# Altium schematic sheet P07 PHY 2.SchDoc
size 420 x 297 mm
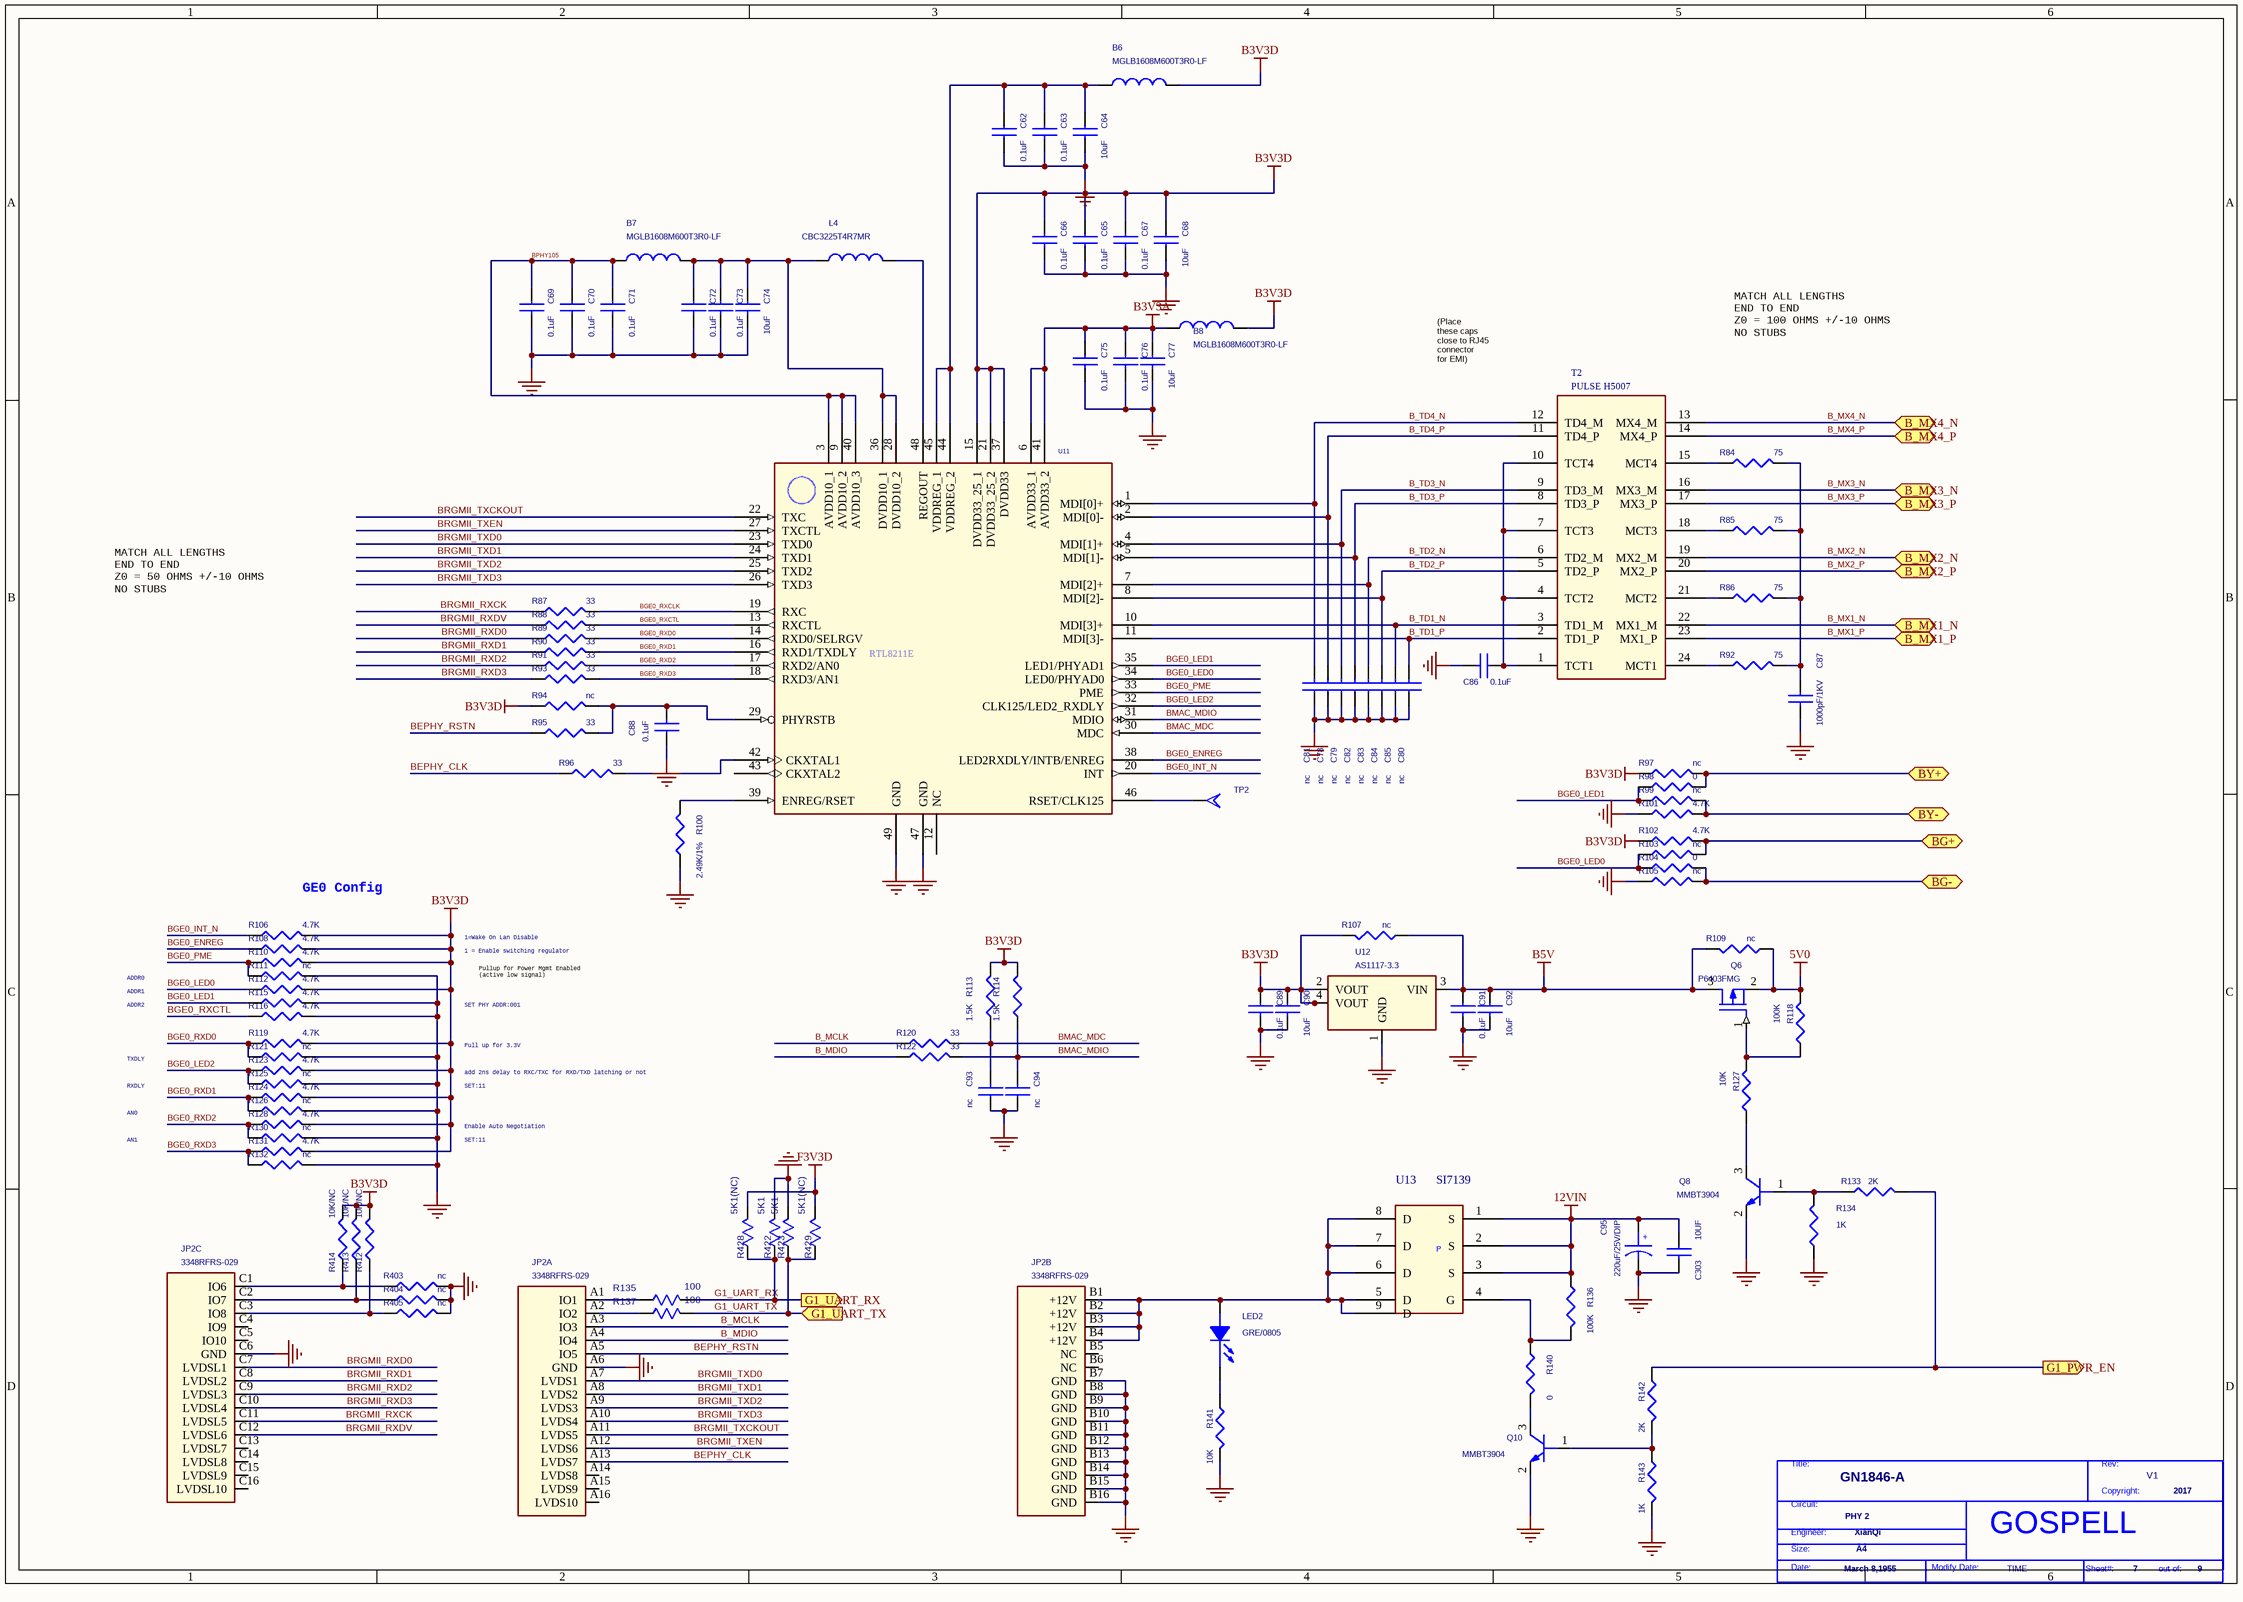
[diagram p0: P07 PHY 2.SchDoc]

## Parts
*  Doc: PHY 2  Page Count: 9  Page Number: 7  Page Create Date: March 8,1955  Page Size: A4  RevCode: V1  Title: GN1846-A  Copyright: 2017  Engineer: XianQi  Page Modify Date: TIME  (hidden comment: GOSPELL)  (graphical)
B6  MGLB1608M600T3R0-LF  [L0603]
B7  MGLB1608M600T3R0-LF  [L0603]
B8  MGLB1608M600T3R0-LF  [L0603]
C62  0.1uF  [0402C]
C63  0.1uF  [0402C]
C64  10uF  [C0603]
C65  0.1uF  [0402C]
C66  0.1uF  [0402C]
C67  0.1uF  [0402C]
C68  10uF  [C0603]
C69  0.1uF  [0402C]
C70  0.1uF  [0402C]
C71  0.1uF  [0402C]
C72  0.1uF  [0402C]
C73  0.1uF  [0402C]
C74  10uF  [C0603]
C75  0.1uF  [0402C]
C76  0.1uF  [0402C]
C77  10uF  [C0603]
C78  nc  [0402C]
C79  nc  [0402C]
C80  nc  [0402C]
C81  nc  [0402C]
C82  nc  [0402C]
C83  nc  [0402C]
C84  nc  [0402C]
C85  nc  [0402C]
C86  0.1uF  [0402C]
C87  1000pF/1KV  [C1206]
C88  0.1uF  [0402C]
C89  0.1uF  [0402C]
C90  10uF  [C0603]
C91  0.1uF  [0402C]
C92  10uF  [C0603]
C93  nc  [0402C]
C94  nc  [0402C]
C95  220uF/25V/DIP  [CE8X3.5]
C303  10UF  [C1206]
JP2  3348RFRS-029  [3348RFRS-029]  (parts A,B,C of 3)
L4  CBC3225T4R7MR  [FB0805]
LED2  GRE/0805  [LED0805]
Q6  P6403FMG  [SOT23]
Q8  MMBT3904  [SOT23]
Q10  MMBT3904  [SOT23]
R84  75  [0402R]
R85  75  [0402R]
R86  75  [0402R]
R87  33  [0402R]
R88  33  [0402R]
R89  33  [0402R]
R90  33  [0402R]
R91  33  [0402R]
R92  75  [0402R]
R93  33  [0402R]
R94  nc  [0402R]
R95  33  [0402R]
R96  33  [0402R]
R97  nc  [0402R]
R98  0  [0402R]
R99  nc  [0402R]
R100  2.49K/1%  [0402R]
R101  4.7K  [0402R]
R102  4.7K  [0402R]
R103  nc  [0402R]
R104  0  [0402R]
R105  nc  [0402R]
R106  4.7K  [0402R]
R107  nc  [R0603]
R108  4.7K  [0402R]
R109  nc  [R0603]
R110  4.7K  [0402R]
R111  nc  [0402R]
R112  4.7K  [0402R]
R113  1.5K  [0402R]
R114  1.5K  [0402R]
R115  4.7K  [0402R]
R116  4.7K  [0402R]
R118  100K  [0402R]
R119  4.7K  [0402R]
R120  33  [0402R]
R121  nc  [0402R]
R122  33  [0402R]
R123  4.7K  [0402R]
R124  4.7K  [0402R]
R125  nc  [0402R]
R126  nc  [0402R]
R127  10K  [0402R]
R128  4.7K  [0402R]
R130  nc  [0402R]
R131  4.7K  [0402R]
R132  nc  [0402R]
R133  2K  [0402R]
R134  1K  [0402R]
R135  100  [0402R]
R136  100K  [R0603]
R137  100  [0402R]
R140  0  [0402R]
R141  10K  [0402R]
R142  2K  [0402R]
R143  1K  [0402R]
R403  nc  [0402R]
R404  nc  [0402R]
R405  nc  [0402R]
R412  10K/NC  [0402R]
R413  10K/NC  [0402R]
R414  10K/NC  [0402R]
R422  5K1  [0402R]
R423  5K1  [0402R]
R428  5K1(NC)  [0402R]
R429  5K1(NC)  [0402R]
T2  PULSE H5007  [H5007-H]
TP2  T POINT A  [TP_G]  (value not drawn)
U11  RTL8211D  [QFN-48P-RTL8211]  (value not drawn)
U12  AS1117-3.3  [SOT223]
U13  SI7139  [PowerPAKSO8]

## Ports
B_MX1_N (bidir), B_MX1_P (bidir), B_MX2_N (bidir), B_MX2_P (bidir), B_MX3_N (bidir), B_MX3_P (bidir), B_MX4_N (bidir), B_MX4_P (bidir), BG+ (bidir), BG- (bidir), BY+ (bidir), BY- (bidir), G1_PWR_EN (out), G1_UART_RX (out), G1_UART_TX (in)

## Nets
5V0: Q6.2(SOURCE) R109.2 R118.1
12VIN: C95.1 C303.1 R136.2 U13.1(S) U13.2(S) U13.3(S)
B3V3A: B8.1 C75.1 C76.1 C77.1 U11.6(AVDD33_1) U11.41(AVDD33_2)
B3V3D: B6.2 B8.2 C65.1 C66.1 C67.1 C68.1 C89.1 C90.1 R94.1 R97.1 R102.1 R106.2 R107.1 R108.2 R110.2 R112.2 R113.2 R114.2 R119.2 R123.2 R124.2 R128.2 R131.2 R412.2 R413.2 R414.2 U11.15(DVDD33_25_1) U11.21(DVDD33_25_2) U11.37(DVDD33) U12.2(VOUT) U12.4(VOUT)
B5V: C91.1 C92.1 Q6.3(DRAIN) R107.2 R109.1 U12.3(VIN)
F3V3D: R428.2(B) R429.2(B)
GND: C62.2 C63.2 C64.2 C65.2 C66.2 C67.2 C68.2 C69.2 C70.2 C71.2 C72.2 C73.2 C74.2 C75.2 C76.2 C77.2 C78.1 C79.1 C80.1 C81.1 C82.1 C83.1 C84.1 C85.1 C86.2 C87.2 C88.1 C89.2 C90.2 C91.2 C92.2 C93.1 C94.1 C95.2 C303.2 JP2.A6(GND) JP2.B7(GND) JP2.B8(GND) JP2.B9(GND) JP2.B10(GND) JP2.B11(GND) JP2.B12(GND) JP2.B13(GND) JP2.B14(GND) JP2.B15(GND) JP2.B16(GND) JP2.C6(GND) Q8.2(EMITTER) Q10.2(EMITTER) R100.1 R101.1 R105.1 R111.2 R115.2 R116.2 R121.2 R125.2 R126.2 R130.2 R132.2 R134.1 R141.1 R143.1 R403.2 R404.2 R405.2 R422.2(B) R423.2(B) U11.47(GND) U11.49(GND) U12.1(GND)
B_MCLK: JP2.A3(IO3) R120.1
B_MDIO: JP2.A4(IO4) R122.1
B_MX1_N: T2.22(MX1_M) ; port B_MX1_N
B_MX1_P: T2.23(MX1_P) ; port B_MX1_P
B_MX2_N: T2.19(MX2_M) ; port B_MX2_N
B_MX2_P: T2.20(MX2_P) ; port B_MX2_P
B_MX3_N: T2.16(MX3_M) ; port B_MX3_N
B_MX3_P: T2.17(MX3_P) ; port B_MX3_P
B_MX4_N: T2.13(MX4_M) ; port B_MX4_N
B_MX4_P: T2.14(MX4_P) ; port B_MX4_P
B_TD1_N: C85.2 T2.3(TD1_M) U11.10(MDI[3]+)
B_TD1_P: C80.2 T2.2(TD1_P) U11.11(MDI[3]-)
B_TD2_N: C83.2 T2.6(TD2_M) U11.7(MDI[2]+)
B_TD2_P: C84.2 T2.5(TD2_P) U11.8(MDI[2]-)
B_TD3_N: C79.2 T2.9(TD3_M) U11.4(MDI[1]+)
B_TD3_P: C82.2 T2.8(TD3_P) U11.5(MDI[1]-)
B_TD4_N: C81.2 T2.12(TD4_M) U11.1(MDI[0]+)
B_TD4_P: C78.2 T2.11(TD4_P) U11.2(MDI[0]-)
BEPHY_CLK: JP2.A13(LVDS7) R96.1
BEPHY_RSTN: JP2.A5(IO5) R95.1
BG+: R102.2 R103.2 ; port BG+
BG-: R104.2 R105.2 ; port BG-
BGE0_ENREG: R108.1 U11.38(LED2RXDLY/INTB/ENREG)
BGE0_INT_N: R106.1 U11.20(INT)
BGE0_LED0: R103.1 R104.1 R112.1 U11.34(LED0/PHYAD0)
BGE0_LED1: R98.1 R99.1 R115.1 U11.35(LED1/PHYAD1)
BGE0_LED2: R123.1 R125.1 U11.32(CLK125/LED2_RXDLY)
BGE0_PME: R110.1 R111.1 U11.33(PME)
BGE0_RXCLK: R87.2 U11.19(RXC)
BGE0_RXCTL: R88.2 R116.1 U11.13(RXCTL)
BGE0_RXD0: R89.2 R119.1 R121.1 U11.14(RXD0/SELRGV)
BGE0_RXD1: R90.2 R124.1 R126.1 U11.16(RXD1/TXDLY)
BGE0_RXD2: R91.2 R128.1 R130.1 U11.17(RXD2/AN0)
BGE0_RXD3: R93.2 R131.1 R132.1 U11.18(RXD3/AN1)
BMAC_MDC: C93.2 R113.1 R120.2 U11.30(MDC)
BMAC_MDIO: C94.2 R114.1 R122.2 U11.31(MDIO)
BPHY105: B7.1 C69.1 C70.1 C71.1 U11.3(AVDD10_1) U11.9(AVDD10_2) U11.40(AVDD10_3)
BRGMII_RXCK: JP2.C11(LVDSL5) R87.1
BRGMII_RXD0: JP2.C7(LVDSL1) R89.1
BRGMII_RXD1: JP2.C8(LVDSL2) R90.1
BRGMII_RXD2: JP2.C9(LVDSL3) R91.1
BRGMII_RXD3: JP2.C10(LVDSL4) R93.1
BRGMII_RXDV: JP2.C12(LVDSL6) R88.1
BRGMII_TXCKOUT: JP2.A11(LVDS5) U11.22(TXC)
BRGMII_TXD0: JP2.A7(LVDS1) U11.23(TXD0)
BRGMII_TXD1: JP2.A8(LVDS2) U11.24(TXD1)
BRGMII_TXD2: JP2.A9(LVDS3) U11.25(TXD2)
BRGMII_TXD3: JP2.A10(LVDS4) U11.26(TXD3)
BRGMII_TXEN: JP2.A12(LVDS6) U11.27(TXCTL)
BY+: R97.2 R98.2 ; port BY+
BY-: R99.2 R101.2 ; port BY-
G1_PWR_EN: R133.2 R142.2 ; port G1_PWR_EN
G1_UART_RX: R135.2(B) R422.1(A) R428.1(A) ; port G1_UART_RX
G1_UART_TX: R137.2(B) R423.1(A) R429.1(A) ; port G1_UART_TX
NetB6_1: B6.1 C62.1 C63.1 C64.1 U11.44(VDDREG_2) U11.45(VDDREG_1)
NetB7_2: B7.2 C72.1 C73.1 C74.1 L4.1 U11.28(DVDD10_2) U11.36(DVDD10_1)
NetC86_1: C86.1 T2.1(TCT1) T2.4(TCT2) T2.7(TCT3) T2.10(TCT4)
NetC87_1: C87.1 R84.2 R85.2 R86.2 R92.2
NetC88_2: C88.2 R94.2 R95.2 U11.29(PHYRSTB)
NetJP2_A1: JP2.A1(IO1) R135.1(A)
NetJP2_A2: JP2.A2(IO2) R137.1(A)
NetJP2_B1: JP2.B1(+12V) JP2.B2(+12V) JP2.B3(+12V) JP2.B4(+12V) LED2.A(ANODE) U13.5(D) U13.6(D) U13.7(D) U13.8(D) U13.9(D)
NetJP2_C1: JP2.C1(IO6) R403.1 R414.1
NetJP2_C2: JP2.C2(IO7) R404.1 R413.1
NetJP2_C3: JP2.C3(IO8) R405.1 R412.1
NetL4_2: L4.2 U11.48(REGOUT)
NetLED2_K: LED2.K(CATHODE) R141.2
NetQ6_1: Q6.1(GATE) R118.2 R127.1
NetQ8_1: Q8.1(BASE) R133.1 R134.2
NetQ8_3: Q8.3(COLLECTOR) R127.2
NetQ10_1: Q10.1(BASE) R142.1 R143.2
NetQ10_3: Q10.3(COLLECTOR) R140.1
NetR84_1: R84.1 T2.15(MCT4)
NetR85_1: R85.1 T2.18(MCT3)
NetR86_1: R86.1 T2.21(MCT2)
NetR92_1: R92.1 T2.24(MCT1)
NetR96_2: R96.2 U11.42(CKXTAL1)
NetR100_2: R100.2 U11.39(ENREG/RSET)
NetR136_1: R136.1 R140.2 U13.4(G)
NetTP2_1: TP2.1(TP) U11.46(RSET/CLK125)

Not connected (* = marked no-connect by the designer): JP2 A14(LVDS8) A15(LVDS9) A16(LVDS10) B5(NC) B6(NC) C4(IO9) C5(IO10) C13(LVDSL7) C14(LVDSL8) C15(LVDSL9) C16(LVDSL10); U11 12(NC) 43(CKXTAL2)

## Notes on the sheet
- (Place
  these caps
  close to RJ45
  connector
  for EMI)
- MATCH ALL LENGTHS
  END TO END
  Z0 = 100 OHMS +/-10 OHMS
  NO STUBS
- MATCH ALL LENGTHS
  END TO END
  Z0 = 50 OHMS +/-10 OHMS
  NO STUBS
- GE0 Config
- 1=Wake On Lan Disable
- ADDR0
- ADDR1
- 1 = Enable switching regulator
- Pullup for Power Mgmt Enabled
  (active low signal)
- ADDR2
- TXDLY
- SET PHY ADDR:001
- Pull up for 3.3V
- add 2ns delay to RXC/TXC for RXD/TXD latching or not
- AN0
- RXDLY
- Enable Auto Negotiation
- SET:11
- AN1

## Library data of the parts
B6-B8 L4 = CHOKE TORROID_0
C62-C94 = CAP NP_Dup1
C95 = CAP POL
C303 = CAP NP
LED2 = LED_0
Q6 = MOSFET P_0
Q8 Q10 = 2N3904
R84-R106 R108 R110-R116 R119-R126 R128 R130-R132 R136 R140-R143 R403-R405 R412-R414 = R_Dup1
R107 R109 R118 R127 R133 R134 = R
R135 R137 R422 R423 R428 R429 = R_1: PARTS: 1; OriginalSymbolOrigin: (10,20); PINSWAP: (A,B); DEVICE: RK73H1JTTD7502F; PKG_TYPE: SR0603; LEVEL: STD; %208%%161%%192%%224%%195%%251%%179%%198%: 片式厚膜电阻器; COMPONENT_HIGH_MAX: 0.55MM; %215%%232%%214%%181%%212%%202%%208%%237%%198%%171%%178%%238%: +/-1%; %182%%238%%182%%168%%185%%166%%194%%202%(W): 0.1; %195%%232%%202%%246%: 片式厚膜电阻器-0.1W-75000OHM-+/-1%-0603; CODE: 7091238
T2 = PULSE H5007_0
U11 = RTL8211D_1
U12 = AS1117-X_1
